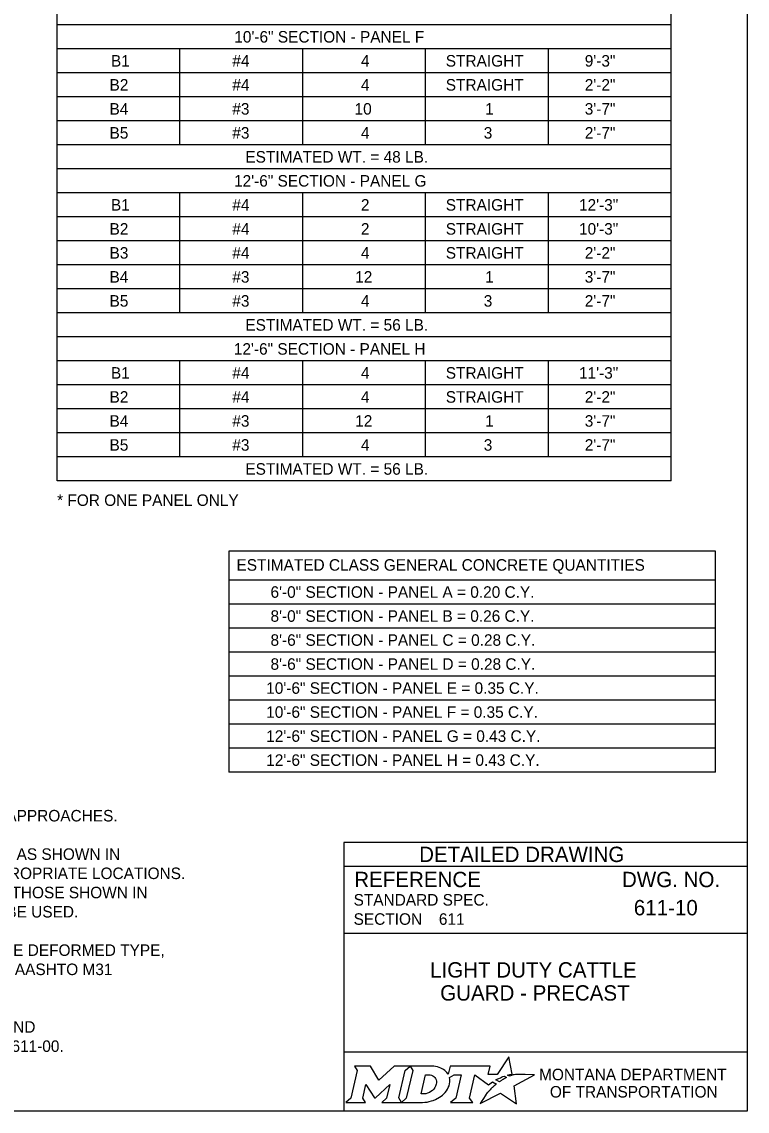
# Model space of a CAD drawing. Extents: x 49991.4 to 50021, y 49987.6 to 50011.4.
# Drawn here: x 50012.97 to 50016.75, y 49987.8 to 49993.47 of the extents above; entities that cross this region are included whole.
import ezdxf

# ---------------------------------------------------------------- set-up
doc = ezdxf.new("R2010")
doc.units = 0
for name, color, linetype in [('Default', 7, 'Continuous'), ('Level 1', 7, 'Continuous'), ('Level 2', 7, 'Continuous'), ('Level 5', 7, 'Continuous')]:
    doc.layers.add(name, color=color, linetype=linetype)

msp = doc.modelspace()

# ---------------------------------------------------------------- linework, layer by layer
at = {"layer": 'Default'}
for points in [[(50015.5126, 49987.9811), (50015.5023, 49987.9867), (50015.5139, 49987.9895), (50015.5255, 49987.9915), (50015.5081, 49988.0816), (50015.4486, 49987.9903), (50015.4013, 49987.9896), (50015.4116, 49988.0337), (50015.2024, 49988.0338), (50015.1923, 49987.9913), (50015.1865, 49987.9996)], [(50014.7056, 49988.0338), (50014.7197, 49988.0104), (50014.6862, 49987.8671), (50014.6605, 49987.8446), (50014.7621, 49987.8446), (50014.7486, 49987.8674), (50014.7648, 49987.9375), (50014.8085, 49987.8685), (50014.8138, 49987.8685), (50014.8889, 49987.938), (50014.8725, 49987.8669), (50014.8478, 49987.8449), (50014.9494, 49987.8449), (50014.9356, 49987.8682), (50014.9688, 49988.0106)], [(50014.9688, 49988.0106), (50014.9941, 49988.0338), (50014.9117, 49988.0338), (50014.8321, 49987.9608), (50014.7876, 49988.0335), (50014.7056, 49988.0338)], [(50015.1077, 49988.0338), (50014.9941, 49988.0338), (50015.0088, 49988.0109), (50014.9749, 49987.8671), (50014.9494, 49987.8449), (50015.06, 49987.8449)], [(50015.1317, 49987.9471), (50015.1305, 49987.939), (50015.1273, 49987.9297), (50015.1231, 49987.9215), (50015.1175, 49987.914), (50015.111, 49987.9071), (50015.1031, 49987.9008), (50015.0948, 49987.8961), (50015.0857, 49987.8922), (50015.0766, 49987.8899), (50015.0674, 49987.889), (50015.0515, 49987.889), (50015.0751, 49987.989), (50015.0911, 49987.989), (50015.0987, 49987.9884), (50015.1063, 49987.9865), (50015.1129, 49987.9835), (50015.119, 49987.9793), (50015.1238, 49987.9743), (50015.1275, 49987.9683), (50015.1302, 49987.9621), (50015.1318, 49987.9547), (50015.1318, 49987.9517), (50015.1317, 49987.9471)], [(50015.1991, 49987.9747), (50015.2237, 49987.9878), (50015.2606, 49987.9878), (50015.232, 49987.8673), (50015.2045, 49987.8446), (50015.3207, 49987.8446), (50015.3037, 49987.8675), (50015.3319, 49987.9877), (50015.4032, 49987.936), (50015.4243, 49987.9511), (50015.444, 49987.9402)], [(50015.3882, 49987.8843), (50015.3729, 49987.8599), (50015.3682, 49987.8524), (50015.3624, 49987.8438), (50015.3601, 49987.8395), (50015.4654, 49987.8926), (50015.5493, 49987.8375), (50015.5362, 49987.9302), (50015.6431, 49987.9886), (50015.5938, 49987.9894), (50015.5637, 49987.9898), (50015.5429, 49987.9901), (50015.5361, 49987.9886), (50015.5312, 49987.9874), (50015.5228, 49987.9851), (50015.5126, 49987.9811)], [(50015.4622, 49987.9535), (50015.4598, 49987.9518), (50015.4415, 49987.9614), (50015.4518, 49987.9671), (50015.4559, 49987.9693), (50015.4645, 49987.9733), (50015.4702, 49987.9759), (50015.4781, 49987.9789), (50015.4854, 49987.9816), (50015.4972, 49987.9742), (50015.4932, 49987.9721), (50015.4886, 49987.9696), (50015.4844, 49987.9674), (50015.4794, 49987.9645), (50015.4775, 49987.9634), (50015.4748, 49987.9618), (50015.4723, 49987.9604), (50015.47, 49987.9588), (50015.4674, 49987.957), (50015.4647, 49987.9552), (50015.4622, 49987.9535)], [(50015.4021, 49987.9004), (50015.4021, 49987.9004)], [(50015.1057, 49987.8522), (50015.1141, 49987.8548), (50015.1271, 49987.8602), (50015.1475, 49987.8712)]]:
    msp.add_lwpolyline(points, dxfattribs=at)
for centre, radius, start, end in [((50015.0868, 49987.9727), 0.1183, 300.9103, 339.1383), ((50015.1308, 49987.9554), 0.0709, 339.5329, 15.8582)]:
    msp.add_arc(centre, radius, start, end, dxfattribs=at)
for centre, major_axis, ratio, start_param, end_param in [((50015.1056, 49987.9864), (0.0834, -0.0037), 0.568097, 0.61298, 1.570796), ((50015.1612, 49987.9937), (0.0361, -0.0295), 0.469099, 1.225588, 1.570796), ((50015.4329, 49987.9305), (-0.0112, -0.0097), 0.021651, 3.157348, 6.283185), ((50015.3952, 49987.8923), (-0.00694, -0.00806), 0.008222, 0, 3.137361), ((50015.4119, 49987.9106), (-0.0098, -0.0102), 0.016458, 3.141593, 6.279097), ((50015.0603, 49987.9932), (0, 0.1484), 0.987302, 3.139398, 3.456847)]:
    msp.add_ellipse(centre, major_axis=major_axis, ratio=ratio, start_param=start_param, end_param=end_param, dxfattribs=at)
at = {"layer": 'Level 1'}
msp.add_lwpolyline([(49999.3835, 49998.9992), (50016.7501, 49998.9992), (50016.7501, 49987.7988), (49999.3835, 49987.7988)], close=True, dxfattribs=at)
at = {"layer": 'Level 2'}
for p, q in [((50013.1565, 49991.0805), (50013.1565, 49998.6599)), ((50016.3545, 49991.0805), (50016.3545, 49998.6599)), ((50016.3545, 49993.4555), (50013.1565, 49993.4555)), ((50016.3545, 49993.3305), (50013.1565, 49993.3305)), ((50013.7961, 49992.8305), (50013.7961, 49993.3305)), ((50014.4357, 49992.8305), (50014.4357, 49993.3305)), ((50015.0753, 49992.8305), (50015.0753, 49993.3305)), ((50015.7149, 49992.8305), (50015.7149, 49993.3305)), ((50016.3545, 49993.2055), (50013.1565, 49993.2055)), ((50016.3545, 49993.0805), (50013.1565, 49993.0805)), ((50016.3545, 49992.9555), (50013.1565, 49992.9555)), ((50016.3545, 49992.8305), (50013.1565, 49992.8305)), ((50016.3545, 49992.7055), (50013.1565, 49992.7055)), ((50016.3545, 49992.5805), (50013.1565, 49992.5805)), ((50013.7961, 49991.9555), (50013.7961, 49992.5805)), ((50014.4357, 49991.9555), (50014.4357, 49992.5805)), ((50015.0753, 49991.9555), (50015.0753, 49992.5805)), ((50015.7149, 49991.9555), (50015.7149, 49992.5805)), ((50016.3545, 49992.4555), (50013.1565, 49992.4555)), ((50016.3545, 49992.3305), (50013.1565, 49992.3305)), ((50016.3545, 49992.2055), (50013.1565, 49992.2055)), ((50016.3545, 49992.0805), (50013.1565, 49992.0805)), ((50016.3545, 49991.9555), (50013.1565, 49991.9555)), ((50016.3545, 49991.8305), (50013.1565, 49991.8305)), ((50016.3545, 49991.7055), (50013.1565, 49991.7055)), ((50013.7961, 49991.2055), (50013.7961, 49991.7055)), ((50014.4357, 49991.2055), (50014.4357, 49991.7055)), ((50015.0753, 49991.2055), (50015.0753, 49991.7055)), ((50015.7149, 49991.2055), (50015.7149, 49991.7055)), ((50016.3545, 49991.5805), (50013.1565, 49991.5805)), ((50016.3545, 49991.4555), (50013.1565, 49991.4555)), ((50016.3545, 49991.3305), (50013.1565, 49991.3305)), ((50016.3545, 49991.2055), (50013.1565, 49991.2055)), ((50016.3545, 49991.0805), (50013.1565, 49991.0805)), ((50016.5846, 49990.7146), (50014.0513, 49990.7146)), ((50014.0513, 49990.7146), (50014.0513, 49989.5646)), ((50016.5846, 49989.5646), (50016.5846, 49990.7146)), ((50016.5846, 49990.5646), (50014.0513, 49990.5646)), ((50016.5846, 49990.4396), (50014.0513, 49990.4396)), ((50016.5846, 49990.3146), (50014.0513, 49990.3146)), ((50016.5846, 49990.1896), (50014.0513, 49990.1896)), ((50016.5846, 49990.0646), (50014.0513, 49990.0646)), ((50016.5846, 49989.9396), (50014.0513, 49989.9396)), ((50016.5846, 49989.8146), (50014.0513, 49989.8146)), ((50016.5846, 49989.6896), (50014.0513, 49989.6896)), ((50016.5846, 49989.5646), (50014.0513, 49989.5646))]:
    msp.add_line(p, q, dxfattribs=at)
at = {"layer": 'Level 5'}
for p, q in [((50016.7501, 49989.1988), (50014.6501, 49989.1988)), ((50014.6501, 49989.1988), (50014.6501, 49987.7988)), ((50016.7501, 49989.0738), (50014.6501, 49989.0738)), ((50016.3862, 49988.8587), (50016.3862, 49988.8587)), ((50015.1444, 49988.7993), (50015.1444, 49988.7993)), ((50016.7501, 49988.7238), (50014.6501, 49988.7238)), ((50015.7001, 49988.4747), (50015.7001, 49988.4747)), ((50016.7501, 49988.1057), (50014.6501, 49988.1057))]:
    msp.add_line(p, q, dxfattribs=at)

# ---------------------------------------------------------------- texts
at = {"layer": 'Default'}
for s, p in [('MONTANA DEPARTMENT', (50015.6663, 49987.96)), ('OF TRANSPORTATION', (50015.7225, 49987.87))]:
    msp.add_text(s, height=0.06, rotation=360, dxfattribs=at).set_placement(p)
at = {"layer": 'Level 2'}
for s, height, p in [('10\'-6" SECTION - PANEL F', 0.06, (50014.0791, 49993.363)), ('B1', 0.06, (50013.4367, 49993.238)), ('#4', 0.06, (50014.0689, 49993.238)), ('4', 0.06, (50014.7385, 49993.238)), ('STRAIGHT', 0.06, (50015.1804, 49993.238)), ('9\'-3"', 0.06, (50015.9041, 49993.238)), ('B2', 0.06, (50013.4293, 49993.113)), ('#4', 0.06, (50014.0689, 49993.113)), ('4', 0.06, (50014.7385, 49993.113)), ('STRAIGHT', 0.06, (50015.1804, 49993.113)), ('2\'-2"', 0.06, (50015.9041, 49993.113)), ('B4', 0.06, (50013.4293, 49992.988)), ('#3', 0.06, (50014.0689, 49992.988)), ('10', 0.06, (50014.7055, 49992.988)), ('1', 0.06, (50015.3855, 49992.988)), ('3\'-7"', 0.06, (50015.9041, 49992.988)), ('B5', 0.06, (50013.4293, 49992.863)), ('#3', 0.06, (50014.0689, 49992.863)), ('4', 0.06, (50014.7385, 49992.863)), ('3', 0.06, (50015.3781, 49992.863)), ('2\'-7"', 0.06, (50015.9041, 49992.863)), ('ESTIMATED WT. = 48 LB.', 0.06, (50014.1367, 49992.738)), ('12\'-6" SECTION - PANEL G', 0.06, (50014.0777, 49992.613)), ('B1', 0.06, (50013.4367, 49992.488)), ('#4', 0.06, (50014.0689, 49992.488)), ('2', 0.06, (50014.7385, 49992.488)), ('STRAIGHT', 0.06, (50015.1804, 49992.488)), ('12\'-3"', 0.06, (50015.8741, 49992.488)), ('B2', 0.06, (50013.4293, 49992.363)), ('#4', 0.06, (50014.0689, 49992.363)), ('2', 0.06, (50014.7385, 49992.363)), ('STRAIGHT', 0.06, (50015.1804, 49992.363)), ('10\'-3"', 0.06, (50015.8741, 49992.363)), ('B3', 0.06, (50013.4293, 49992.238)), ('#4', 0.06, (50014.0689, 49992.238)), ('4', 0.06, (50014.7385, 49992.238)), ('STRAIGHT', 0.06, (50015.1804, 49992.238)), ('2\'-2"', 0.06, (50015.9041, 49992.238)), ('B4', 0.06, (50013.4293, 49992.113)), ('#3', 0.06, (50014.0689, 49992.113)), ('12', 0.06, (50014.7085, 49992.113)), ('1', 0.06, (50015.3855, 49992.113)), ('3\'-7"', 0.06, (50015.9041, 49992.113)), ('B5', 0.06, (50013.4293, 49991.988)), ('#3', 0.06, (50014.0689, 49991.988)), ('4', 0.06, (50014.7385, 49991.988)), ('3', 0.06, (50015.3781, 49991.988)), ('2\'-7"', 0.06, (50015.9041, 49991.988)), ('ESTIMATED WT. = 56 LB.', 0.06, (50014.1367, 49991.863)), ('12\'-6" SECTION - PANEL H', 0.06, (50014.0767, 49991.738)), ('B1', 0.06, (50013.4367, 49991.613)), ('#4', 0.06, (50014.0689, 49991.613)), ('4', 0.06, (50014.7385, 49991.613)), ('STRAIGHT', 0.06, (50015.1804, 49991.613)), ('11\'-3"', 0.06, (50015.8741, 49991.613)), ('B2', 0.06, (50013.4293, 49991.488)), ('#4', 0.06, (50014.0689, 49991.488)), ('4', 0.06, (50014.7385, 49991.488)), ('STRAIGHT', 0.06, (50015.1804, 49991.488)), ('2\'-2"', 0.06, (50015.9041, 49991.488)), ('B4', 0.06, (50013.4293, 49991.363)), ('#3', 0.06, (50014.0689, 49991.363)), ('12', 0.06, (50014.7085, 49991.363)), ('1', 0.06, (50015.3855, 49991.363)), ('3\'-7"', 0.06, (50015.9041, 49991.363)), ('B5', 0.06, (50013.4293, 49991.238)), ('#3', 0.06, (50014.0689, 49991.238)), ('4', 0.06, (50014.7385, 49991.238)), ('3', 0.06, (50015.3781, 49991.238)), ('2\'-7"', 0.06, (50015.9041, 49991.238)), ('ESTIMATED WT. = 56 LB.', 0.06, (50014.1367, 49991.113)), ('* FOR ONE PANEL ONLY', 0.06, (50013.1565, 49990.9505)), ('ESTIMATED CLASS GENERAL CONCRETE QUANTITIES', 0.06, (50014.0905, 49990.6132)), (' 6\'-0" SECTION - PANEL A = 0.20 C.Y.', 0.06, (50014.2453, 49990.4721)), (' 8\'-0" SECTION - PANEL B = 0.26 C.Y.', 0.06, (50014.2453, 49990.3471)), (' 8\'-6" SECTION - PANEL C = 0.28 C.Y.', 0.06, (50014.2453, 49990.2221)), (' 8\'-6" SECTION - PANEL D = 0.28 C.Y.', 0.06, (50014.2453, 49990.0971)), ('10\'-6" SECTION - PANEL E = 0.35 C.Y.', 0.06, (50014.2453, 49989.9721)), ('10\'-6" SECTION - PANEL F = 0.35 C.Y.', 0.06, (50014.2453, 49989.8471)), ('12\'-6" SECTION - PANEL G = 0.43 C.Y.', 0.06, (50014.2453, 49989.7221)), ('12\'-6" SECTION - PANEL H = 0.43 C.Y.', 0.06, (50014.2453, 49989.5971)), ('USE ONLY ON FIELD OR PRIVATE APPROACHES.', 0.06, (50011.5634, 49989.3075)), ('PROVIDE CAST-IN ANCHOR BOLTS AS SHOWN IN', 0.06, (50011.5634, 49989.1075)), ('DTL. DWG. NO. 611-00 AT THE APPROPRIATE LOCATIONS.', 0.06, (50011.5634, 49989.0075)), ('CAST-IN LAG PLATES, SIMILAR TO THOSE SHOWN IN', 0.06, (50011.5634, 49988.9075)), ('611-10', 0.08, (50016.1596, 49988.8187)), ('DTL. DWG. NO. 611-15, MAY ALSO BE USED.', 0.06, (50011.5634, 49988.8075)), ('611', 0.06, (50015.1444, 49988.7693)), ('ALL REINFORCING STEEL IS OF THE DEFORMED TYPE,', 0.06, (50011.5634, 49988.6075)), ('MEETING THE REQUIREMENTS OF AASHTO M31', 0.06, (50011.5634, 49988.5075)), ('LIGHT DUTY CATTLE ', 0.08, (50015.0988, 49988.4947)), ('GUARD - PRECAST', 0.08, (50015.1512, 49988.3747)), ('FOR DETAILS OF STEEL GRATES AND', 0.06, (50011.5634, 49988.2075)), ('STEEL WINGS SEE DTL. DWG. NO. 611-00.', 0.06, (50011.5634, 49988.1075))]:
    msp.add_text(s, height=height, dxfattribs=at).set_placement(p)
at = {"layer": 'Level 5'}
for s, height, p in [('DETAILED DRAWING', 0.0799, (50015.0418, 49989.0963)), ('REFERENCE', 0.08, (50014.7037, 49988.9654)), ('DWG. NO.', 0.08, (50016.0979, 49988.9654)), ('STANDARD SPEC.', 0.06, (50014.7004, 49988.8694)), ('SECTION', 0.06, (50014.7004, 49988.7694))]:
    msp.add_text(s, height=height, dxfattribs=at).set_placement(p)

doc.saveas('drawing.dxf')
